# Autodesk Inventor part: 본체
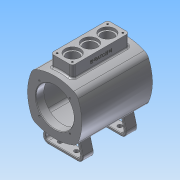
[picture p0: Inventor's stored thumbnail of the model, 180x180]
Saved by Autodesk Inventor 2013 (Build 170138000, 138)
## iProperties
Created: 2015-11
Part Number: 본체
Material: 알루미늄 6061
Document SubType Name: Modeling
Designer: mduedu
Density: 2.71 g/cm^3
Mass: 1109.75 g
Surface Area: 1165.93 cm^2
Volume: 409.503 cm^3
Author: mduedu
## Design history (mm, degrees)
sketch "스케치2"
  geometry: L1 (0, 250)-(0, -250); L2 (250, 0)-(-250, 0); L3 (-50, 50)-(50, 50); L4 (50, 50)-(50, -50); L5 (50, -50)-(-50, -50); L6 (-50, -50)-(-50, 50); A1 r 90 centre (-40, 0) between (40.415, -40.415) and (40.415, 40.415); A2 r 90 centre (40, 0) between (-40.415, 40.415) and (-40.415, -40.415); A3 r 90 centre (0, -40) between (40.415, 40.415) and (-40.415, 40.415); A4 r 90 centre (0, 40) between (-40.415, -40.415) and (40.415, -40.415); 2 further points
  constraints: 12 end point, 8 point on circle, 4 centre point, 4 tangent, 3 perpendicular, 2 horizontal alignment, 2 midpoint, 2 parallel, 2 symmetric about line, 1 coincident, 1 equal radius, 1 horizontal, 1 vertical, 1 vertical alignment, 2 other
  dimensions: "d6" = 500 distance of L1.start L1.end; "d8" = 500 distance of L2.start L2.end; "d9" = 100 distance of L3.end L4.end; "d11" = 90 radius of A3
extrude "돌출1" new body sketch "스케치2" stored distance "d12" = 130; taper "d13" = 0 deg
fillet "모깎기6" dims "d30" = 15
feature "쉘1" dims "d31" = 15, "d32" = 6, "d33" = 15
sketch "스케치5"
  geometry: C1 r 35 at (0, 0); 1 further point
  constraints: 1 centre point, 1 coincident
  dimensions: "d34" = 70 diameter of C1
extrude "돌출3" cut sketch "스케치5" stored distance "d36" = 3; taper "d37" = 0 deg
fillet "모깎기14" dims "d78" = 3
sketch "스케치12"
  geometry: L1 (0, 0)-(28.284, 28.284); L2 (0, 0)-(40, 0); A1 r 40 centre (0, 0) between (28.284, 28.284) and (40, 0); 2 further points
  constraints: 4 end point, 2 coincident, 2 point on circle, 1 centre point, 1 horizontal
  dimensions: "d79" = 80 diameter of A1; "d80" = 45 deg angle of L2 L1
hole "구멍2" sketch "스케치12" at (28.284, 28.284) diameter "d82" = 3.242; stored, may be unused: countersink angle "d86" = 90 deg, drill point angle "d88" = 118 deg; dims "d83" = 9, "d84" = 10, "d85" = 2, "d87" = 11
node "작업 평면2"
sketch "스케치13"
  geometry: L1 (-52.5, -20)-(52.5, -20); L2 (52.5, -20)-(52.5, 20); L3 (52.5, 20)-(-52.5, 20); L4 (-52.5, 20)-(-52.5, -20); L5 (-52.5, -20)-(52.5, 20); L6 (52.5, -20)-(-52.5, 20); 1 further point
  constraints: 12 end point, 2 midpoint, 2 parallel, 1 horizontal, 1 perpendicular
  dimensions: "d93" = 105 distance of L2.end L3.end; "d95" = 40 distance of L1.end L2.end
extrude "돌출8" join sketch "스케치13" stored distance "d96" = 80; taper "d97" = 0 deg
fillet "모깎기15" dims "d98" = 5
fillet "모깎기16" dims "d99" = 3
sketch "스케치14"
  geometry: L1 (-52.5, 15)-(-52.5, -15) reference; L2 (52.5, -15)-(52.5, 15) reference; L3 (-52.5, 0)-(52.5, 0); 4 further points
  constraints: 2 end point, 2 midpoint, 2 point on line, 1 coincident
  dimensions: "d100" = 32 distance of point (-32, 0) point (0, 0); "d102" = 32 distance of point (32, 0) point (0, 0) (derived)
hole "구멍3" sketch "스케치14" at (-32, 0), (0, 0), (32, 0) diameter "d103" = 22; stored, may be unused: countersink angle "d107" = 90 deg, drill point angle "d109" = 118 deg; dims "d104" = 8, "d105" = 28, "d106" = 5, "d108" = 10
sketch "스케치15"
  geometry: L1 (46.5, -14)-(-46.5, -14); L2 (-46.5, -14)-(-46.5, 14); L3 (-46.5, 14)-(46.5, 14); L4 (46.5, 14)-(46.5, -14); L5 (46.5, -14)-(-46.5, 14); L6 (-46.5, -14)-(46.5, 14); L7 (47.5, 20)-(-47.5, 20) reference; L8 (-52.5, 15)-(-52.5, -15) reference; 5 further points
  constraints: 12 end point, 4 coincident, 2 midpoint, 2 parallel, 1 horizontal, 1 perpendicular
  dimensions: "d110" = 6 distance between parallel lines of L3 L7; "d111" = 6 distance between parallel lines of L2 L8
hole "구멍4" sketch "스케치15" at (-46.5, 14), (46.5, 14), (46.5, -14), (-46.5, -14) diameter "d112" = 3.242; stored, may be unused: countersink angle "d116" = 90 deg, drill point angle "d118" = 118 deg; dims "d113" = 10, "d114" = 28, "d115" = 5, "d117" = 13
sketch "스케치16"
  geometry: L1 (33.5, 0)-(61.5, 0) reference; 2 further points
  constraints: 1 vertical alignment, 1 other
  dimensions: "d128" = 11 distance from line of L1 point (47.5, -11)
feature "엠보싱2" sketch "스케치16" dims "d6" = 500, "d8" = 500, "d9" = 100, "d11" = 90, "d34" = 70, "d123" = 0.5, "d124" = 0
chamfer "모따기1" distance "d125" = 1; stored, may be unused: second distance "d126" = 2, angle "d127" = 45 deg
sketch "스케치18"
  geometry: L1 (0, 0)-(0, -80); L2 (40, -80)-(30.531, -44.663); L3 (-40, -80)-(-30.531, -44.663); L4 (-40, -80)-(40, -80); A1 r 90 centre (0, 40) between (-34.941, -42.941) and (34.941, -42.941) reference; A2 r 90 centre (0, 40) between (-30.531, -44.663) and (30.531, -44.663)
  constraints: 8 end point, 3 point on circle, 2 symmetric about line, 1 centre point, 1 coincident, 1 midpoint, 1 perpendicular, 1 vertical
  dimensions: "d132" = 80 distance of L3.start L2.start; "d134" = 75 deg angle of L4 L2; "d136" = 80 distance of L1.start L1.end
extrude "돌출9" new body sketch "스케치18" stored distance "d137" = 100; taper "d138" = 0 deg
fillet "모깎기17" dims "d139" = 10
sketch "스케치19"
  geometry: L1 (26.968, -80)-(-26.968, -80) reference; L2 (-36.627, -67.412)-(-30.531, -44.663) reference; L3 (30.531, -44.663)-(36.627, -67.412) reference; L4 (-25.775, -46.23)-(-31.797, -68.706); L5 (-26.968, -75)-(26.968, -75); L6 (31.797, -68.706)-(25.775, -46.23); L7 (0, 0)-(0, -80); A1 r 10 centre (26.968, -70) between (26.968, -80) and (36.627, -67.412) reference; A2 r 10 centre (-26.968, -70) between (-36.627, -67.412) and (-26.968, -80) reference; A3 r 90 centre (0, 40) between (-30.531, -44.663) and (30.531, -44.663) reference; A4 r 5 centre (-26.968, -70) between (-31.797, -68.706) and (-26.968, -75); A5 r 5 centre (26.968, -70) between (26.968, -75) and (31.797, -68.706); A6 r 90 centre (0, 40) between (-25.775, -46.23) and (25.775, -46.23)
  constraints: 8 end point, 7 point on circle, 3 centre point, 2 parallel, 1 coincident, 1 midpoint, 1 symmetric about line, 1 tangent, 2 other
  dimensions: "d140" = 5 distance between parallel lines of L1 L5
extrude "돌출10" cut sketch "스케치19" stored distance "d141" = 100; taper "d142" = 0 deg
sketch "스케치20"
  geometry: L1 (-30, 0)-(30, 0); L2 (30, 0)-(30, -90); L3 (30, -90)-(-30, -90); L4 (-30, -90)-(-30, 0); L5 (50, -80)-(-50, -80) reference; 2 further points
  constraints: 8 end point, 2 parallel, 1 coincident, 1 horizontal, 1 midpoint, 1 perpendicular
  dimensions: "d143" = 10 distance from line of L5 L2.end; "d144" = 60 distance of L2.end L3.end
extrude "돌출11" cut sketch "스케치20" stored distance "d145" = 100; taper "d146" = 0 deg
sketch "스케치21"
  geometry: L1 (0, 26.968)-(100, 26.968); L2 (100, 53.935)-(100, 0) reference; L3 (0, 0)-(0, 53.935) reference; L4 (0, 53.935)-(20, 53.935) reference; L5 (20, 0)-(0, 0) reference; L6 (115, 76.968)-(-15, 76.968) reference; L7 (115, -23.032)-(-15, -23.032) reference; L8 (10, 53.935)-(10, 0); L9 (50, 76.968)-(50, -23.032); C1 r 4 at (10, 41.968); C2 r 4 at (10, 11.968); C3 r 4 at (90, 41.968); C4 r 4 at (90, 11.968); 2 further points
  constraints: 6 end point, 6 midpoint, 4 centre point, 3 symmetric about line, 1 coincident, 1 horizontal, 1 point on line, 3 other
  dimensions: "d147" = 8 diameter of C1; "d148" = 15 distance from line of C1.centre L1
extrude "돌출12" cut sketch "스케치21" stored distance "d149" = 100; taper "d150" = 0 deg
feature "결합2"
  node "솔리드3"
fillet "모깎기18" dims "d151" = 1
fillet "모깎기19" dims "d152" = 2
node "솔리드1"
pattern_circular "원형 패턴1" dims angle "d90" = 360 deg
mirror "대칭3"
node "투영된 루프1"
